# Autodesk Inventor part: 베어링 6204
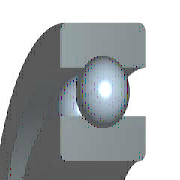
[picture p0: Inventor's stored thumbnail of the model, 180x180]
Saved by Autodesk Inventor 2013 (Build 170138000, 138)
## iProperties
IsCustomPart: 0
Manager: KYOUNG IL JANG
Company: 한국ATC센터
Created: 2009-02
Part Number: 베어링 6204
Material: Steel, Mild
Description: 깊은 그루브 볼 베어링
Document SubType Name: Modeling
Standard: KS B 2023
Standards Organization: KS
Language: ko-KR
Size Designation: 6204 - 20 x 47 x 14
Categories: <MemberInstance><Categories><Category DisplayName="샤프트 부품" InternalName="7f7aeb1f-a693-4053-b835-cee3144e0d98" Mnemonic="SHFT"><Category DisplayName="베어링" Inter
Density: 1 g/cm^3
Checked By: KYOUNG IL JANG
Vendor: CBT Solutions
Designer: KYOUNG IL JANG
Author: KYOUNG IL JANG
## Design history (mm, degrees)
sketch "스케치" dims "d0" = 7.02 (= -0.26 x WD + 0.26 x BD)
  geometry: L1 (3.49, 16.75)-(10.51, 16.75); L2 (7, 16.75)-(7, 13.24); L3 (7, 16.75)-(7, 20.26); L4 (4.392, 14.401)-(0, 14.401); L5 (0, 10)-(14, 10); L6 (4.392, 19.099)-(0, 19.099); L7 (0, 23.5)-(14, 23.5); L8 (14, 10)-(14, 14.401); L9 (9.608, 14.401)-(14, 14.401); L10 (9.608, 19.099)-(14, 19.099); L11 (14, 23.5)-(14, 19.099); L12 (-1.4, 0)-(8.4, 0) reference; L13 (0, -0.3)-(0, 5.3) reference
  constraints: 22 end point, 4 point on line, 2 collinear, 2 perpendicular, 2 symmetric about line, 1 midpoint, 1 parallel, 14 other
  dimensions: "d9" = 20 diameter of L5 L12 (= WD); "d11" = 47 diameter of L7 L12 (= BD); "d12" = 14 distance between parallel lines of L8 L13 (= KB); "d13" = 28.802 diameter of L9 L12 (= 0.326 x BD + 0.674 x WD)
revolve "본체" stored, may be unused: angle "d6" = 90 deg
revolve "볼" stored, may be unused: angle "d7" = 90 deg
pattern_circular "IDS_ARRAYBALL[SIMPL:T]" dims angle "d3" = 360 deg
body "Solid1"
fillet "모깎기1" dims "d1" = 1 (= KRS)
other parameters: "WD" = 20 [user parameter; used in 5 equation terms], "BD" = 47 [user parameter; used in 5 equation terms], "KB" = 14 [user parameter; used in 1 equation term], "KRS" = 1 [user parameter; used in 1 equation term], "d4" = 0, "d5" = 0, "d8" = 0, "d14" = 0, "d15" = 0, "BBA" = 0 [user parameter], "BC0" = 6550000 [user parameter], "BC" = 1.27e+07 [user parameter], "BR" = 23.5 (= 0.5 x BD) [user parameter]
